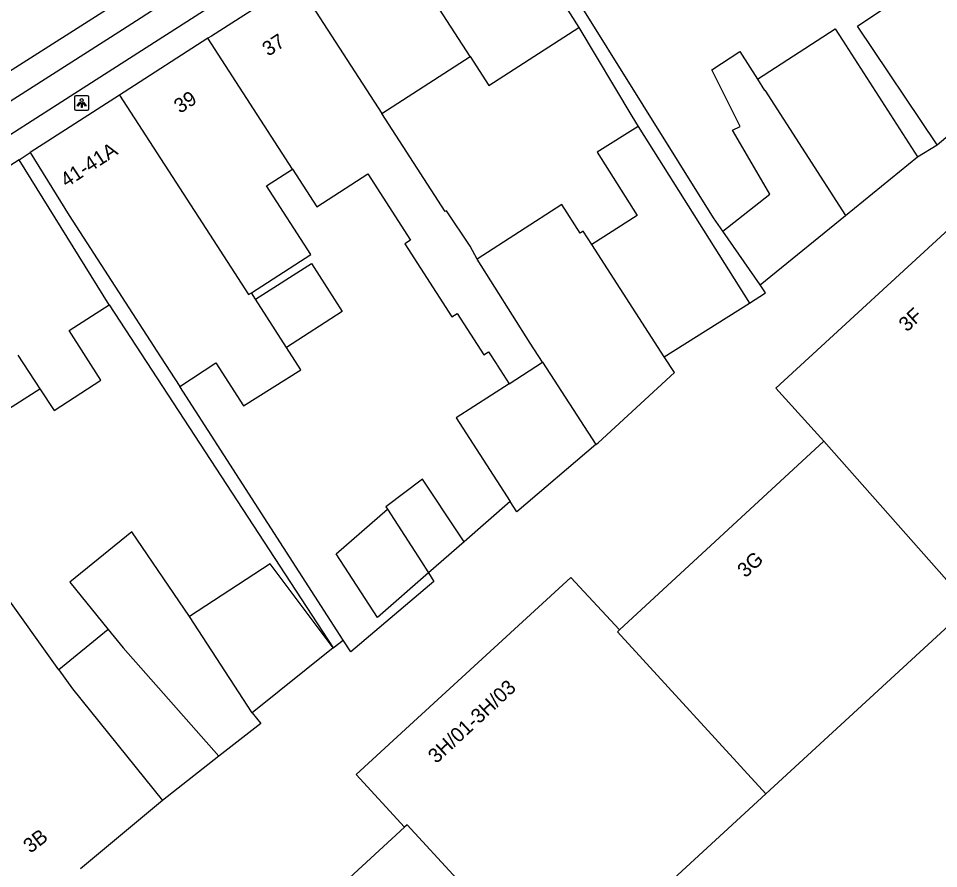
# Model space of a CAD drawing. Extents: x 159503 to 160347, y 382525 to 383272.
# Drawn here: x 159815.5 to 159878.7, y 383112.7 to 383171.1 of the extents above; entities that cross this region are included whole.
import ezdxf

# ---------------------------------------------------------------- set-up
doc = ezdxf.new("R2010")
doc.units = 0
for name, color, linetype in [('IMGEO_Lichtpunt', 7, 'Continuous'), ('IMGEO_Pand', 7, 'Continuous'), ('IMGEO_Pand_nummerreeks', 7, 'Continuous'), ('IMGEO_Rijbaan_lokaal_gesloten', 7, 'Continuous'), ('IMGEO_Rijbaan_lokaal_open', 7, 'Continuous'), ('IMGEO_Voetpad_open', 7, 'Continuous')]:
    doc.layers.add(name, color=color, linetype=linetype)

msp = doc.modelspace()

# ---------------------------------------------------------------- linework, layer by layer
at = {"layer": 'IMGEO_Lichtpunt'}
for p, q in [((159820.226, 383165.788), (159819.418, 383165.788)), ((159820.226, 383165.788), (159819.418, 383165.788)), ((159819.324, 383165.693), (159819.324, 383164.886)), ((159819.324, 383165.693), (159819.324, 383164.886)), ((159820.32, 383164.886), (159820.32, 383165.693)), ((159820.32, 383164.886), (159820.32, 383165.693)), ((159819.418, 383164.792), (159820.226, 383164.792)), ((159819.418, 383164.792), (159820.226, 383164.792))]:
    msp.add_line(p, q, dxfattribs=at)
for points in [[(159819.698, 383165.357), (159819.737, 383165.329), (159819.549, 383165.067), (159819.511, 383165.094), (159819.698, 383165.357)], [(159819.8, 383165.309), (159819.847, 383165.309), (159819.847, 383164.987), (159819.8, 383164.987), (159819.8, 383165.309)], [(159819.91, 383165.329), (159819.948, 383165.356), (159820.135, 383165.094), (159820.096, 383165.066), (159819.91, 383165.329)]]:
    msp.add_lwpolyline(points, dxfattribs=at)
msp.add_circle((159819.823, 383165.491), 0.0994, dxfattribs=at)
for centre, start, end in [((159819.418, 383165.693), 90, 180), ((159819.418, 383165.693), 90, 180), ((159820.226, 383165.693), 0, 90), ((159820.226, 383165.693), 0, 90), ((159819.418, 383164.886), 180, 270), ((159819.418, 383164.886), 180, 270), ((159820.226, 383164.886), 270, 0), ((159820.226, 383164.886), 270, 360)]:
    msp.add_arc(centre, 0.0946, start, end, dxfattribs=at)
at = {"layer": 'IMGEO_Pand'}
for points in [[(159846.963, 383181.604), (159847.147, 383181.308), (159854.007, 383170.489)], [(159846.533, 383168.49), (159840.668, 383177.557)], [(159834.587, 383173.647), (159828.738, 383169.887), (159828.505, 383169.737)], [(159834.587, 383173.647), (159840.463, 383164.563)], [(159878.649, 383162.412), (159873.157, 383170.573), (159878.113, 383173.909), (159882.802, 383166.958)], [(159846.533, 383168.49), (159847.826, 383166.49), (159854.007, 383170.489)], [(159866.281, 383166.939), (159871.638, 383170.377), (159872.138, 383169.598), (159877.286, 383161.578)], [(159828.505, 383169.737), (159822.755, 383166.043), (159822.422, 383165.829)], [(159834.32, 383160.746), (159828.505, 383169.737)], [(159840.463, 383164.563), (159846.533, 383168.49)], [(159863.901, 383156.471), (159867.142, 383159.027), (159866.569, 383160.002), (159864.566, 383163.412), (159865.098, 383163.68), (159863.142, 383167.579), (159865.074, 383168.819), (159866.281, 383166.939)], [(159866.281, 383166.939), (159866.781, 383166.16), (159866.8, 383166.172), (159872.333, 383157.555)], [(159878.649, 383162.412), (159883.243, 383166.304), (159882.802, 383166.958)], [(159822.422, 383165.829), (159816.292, 383161.895)], [(159822.422, 383165.829), (159828.611, 383156.262), (159831.293, 383152.117), (159831.489, 383152.244)], [(159847.026, 383154.562), (159846.526, 383155.446), (159844.898, 383157.869), (159844.824, 383157.821), (159840.463, 383164.563)], [(159858.078, 383163.683), (159855.275, 383161.92), (159858.016, 383157.566), (159854.898, 383155.557)], [(159858.078, 383163.683), (159865.729, 383151.527)], [(159815.518, 383161.374), (159809.323, 383157.389)], [(159821.723, 383151.405), (159815.518, 383161.374)], [(159816.292, 383161.895), (159818.963, 383157.559), (159825.248, 383147.845), (159826.569, 383145.796)], [(159872.333, 383157.555), (159877.286, 383161.578)], [(159831.489, 383152.244), (159835.57, 383154.884), (159832.528, 383159.587), (159834.32, 383160.746)], [(159834.32, 383160.746), (159835.994, 383158.159), (159839.487, 383160.419), (159842.429, 383155.87), (159842.038, 383155.618), (159845.273, 383150.594), (159845.636, 383150.827), (159847.474, 383147.973), (159847.805, 383148.187), (159848.373, 383147.305), (159848.399, 383147.266), (159849.22, 383145.991)], [(159870.856, 383142.052), (159867.552, 383145.679), (159882.293, 383159.226), (159885.592, 383155.616), (159885.667, 383155.685)], [(159854.898, 383155.557), (159854.306, 383156.473), (159854.104, 383156.343), (159852.839, 383158.308), (159847.026, 383154.562)], [(159866.464, 383152.788), (159872.333, 383157.555)], [(159866.464, 383152.788), (159863.901, 383156.471)], [(159859.884, 383147.849), (159854.898, 383155.557)], [(159851.519, 383147.471), (159850.669, 383148.784), (159847.026, 383154.562)], [(159831.778, 383151.794), (159835.614, 383154.255), (159837.732, 383150.953), (159833.896, 383148.492)], [(159831.778, 383151.794), (159831.489, 383152.244)], [(159816.95, 383145.641), (159817.927, 383144.161), (159821.142, 383146.24), (159818.969, 383149.649), (159821.723, 383151.405)], [(159833.896, 383148.492), (159831.778, 383151.794)], [(159859.884, 383147.849), (159865.729, 383151.527)], [(159826.569, 383145.796), (159829.055, 383147.432), (159830.946, 383144.483), (159834.882, 383146.955), (159833.896, 383148.492)], [(159815.427, 383147.946), (159816.95, 383145.641)], [(159849.22, 383145.991), (159851.519, 383147.471)], [(159851.519, 383147.471), (159855.182, 383141.808)], [(159855.182, 383141.808), (159855.327, 383141.931), (159860.586, 383146.764), (159859.884, 383147.849)], [(159812.978, 383146.383), (159814.464, 383144.054), (159816.95, 383145.641)], [(159849.22, 383145.991), (159845.58, 383143.646), (159849.281, 383137.9)], [(159855.182, 383141.808), (159849.741, 383137.186), (159849.281, 383137.9)], [(159856.801, 383129.073), (159870.856, 383142.052)], [(159870.856, 383142.052), (159880.894, 383130.711)], [(159846.118, 383135.124), (159845.752, 383135.675), (159843.26, 383139.426), (159840.726, 383137.536), (159840.84, 383137.361)], [(159843.663, 383132.992), (159840.161, 383129.933), (159837.329, 383134.295), (159840.84, 383137.361)], [(159840.84, 383137.361), (159843.189, 383133.743), (159843.616, 383133.066), (159843.663, 383132.992)], [(159818.244, 383126.331), (159810.452, 383137.218)], [(159827.227, 383129.995), (159823.282, 383135.814), (159819.011, 383132.358), (159821.655, 383129.092)], [(159846.118, 383135.124), (159843.663, 383132.992)], [(159837.117, 383127.828), (159832.782, 383133.613), (159827.227, 383129.995)], [(159842.011, 383115.506), (159838.687, 383119.121), (159842.37, 383122.504), (159853.447, 383132.681), (159856.801, 383129.073)], [(159880.894, 383130.711), (159866.864, 383117.803)], [(159831.542, 383123.365), (159827.227, 383129.995)], [(159821.655, 383129.092), (159818.244, 383126.331)], [(159821.655, 383129.092), (159822.671, 383127.837), (159829.264, 383120.384)], [(159856.801, 383129.073), (159856.653, 383128.937), (159866.864, 383117.803)], [(159837.117, 383127.828), (159831.542, 383123.365)], [(159818.244, 383126.331), (159819.185, 383125.016), (159825.39, 383117.349)], [(159831.542, 383123.365), (159832.132, 383122.629), (159829.264, 383120.384)], [(159829.264, 383120.384), (159825.39, 383117.349)], [(159866.864, 383117.803), (159852.451, 383104.542)], [(159825.39, 383117.349), (159819.75, 383112.651)], [(159842.011, 383115.506), (159828.063, 383102.657)], [(159852.451, 383104.542), (159842.194, 383115.675), (159842.011, 383115.506)]]:
    msp.add_lwpolyline(points, dxfattribs=at)
at = {"layer": 'IMGEO_Rijbaan_lokaal_gesloten'}
for points in [[(159783.129, 383148.501), (159789.43, 383151.698), (159793.256, 383153.812), (159796.935, 383156.075), (159802.071, 383159.31), (159806.3, 383162.05), (159813.325, 383166.51), (159823.487, 383172.985), (159829.121, 383176.57), (159840.622, 383183.949), (159853.667, 383192.289)], [(159807.939, 383160.989), (159813.8, 383164.72), (159822.635, 383170.351), (159828.873, 383174.384)]]:
    msp.add_lwpolyline(points, dxfattribs=at)
at = {"layer": 'IMGEO_Rijbaan_lokaal_open'}
for points in [[(159877.286, 383161.578), (159878.649, 383162.412)], [(159865.729, 383151.527), (159866.85, 383152.233), (159866.464, 383152.788)], [(159849.281, 383137.9), (159846.118, 383135.124)], [(159843.663, 383132.992), (159844.036, 383132.404), (159838.318, 383127.572), (159837.8, 383128.375)], [(159837.117, 383127.828), (159837.8, 383128.375)]]:
    msp.add_lwpolyline(points, dxfattribs=at)
at = {"layer": 'IMGEO_Voetpad_open'}
for points in [[(159863.901, 383156.471), (159863.26, 383157.393), (159853.585, 383172.908)], [(159829.345, 383172.324), (159821.969, 383167.609), (159809.636, 383159.722)], [(159854.007, 383170.489), (159857.639, 383164.38), (159858.078, 383163.683)], [(159815.518, 383161.374), (159816.292, 383161.895)], [(159821.723, 383151.405), (159837.117, 383127.828)], [(159837.8, 383128.375), (159826.569, 383145.796)]]:
    msp.add_lwpolyline(points, dxfattribs=at)

# ---------------------------------------------------------------- texts
at = {"layer": 'IMGEO_Pand_nummerreeks'}
for s, rotation, p in [('37', 32.90497, (159832.651, 383168.463)), ('39', 32.89924, (159826.58, 383164.537)), ('41-41A', 33.04248, (159818.78, 383159.456)), ('3F', 42.58305, (159876.566, 383149.508)), ('3G', 42.72073, (159865.465, 383132.609)), ('3H/01-3H/03', 42.89449, (159844.206, 383119.839)), ('3B', 37.60322, (159816.293, 383113.679))]:
    msp.add_text(s, height=1, rotation=rotation, dxfattribs=at).set_placement(p)

doc.saveas('drawing.dxf')
